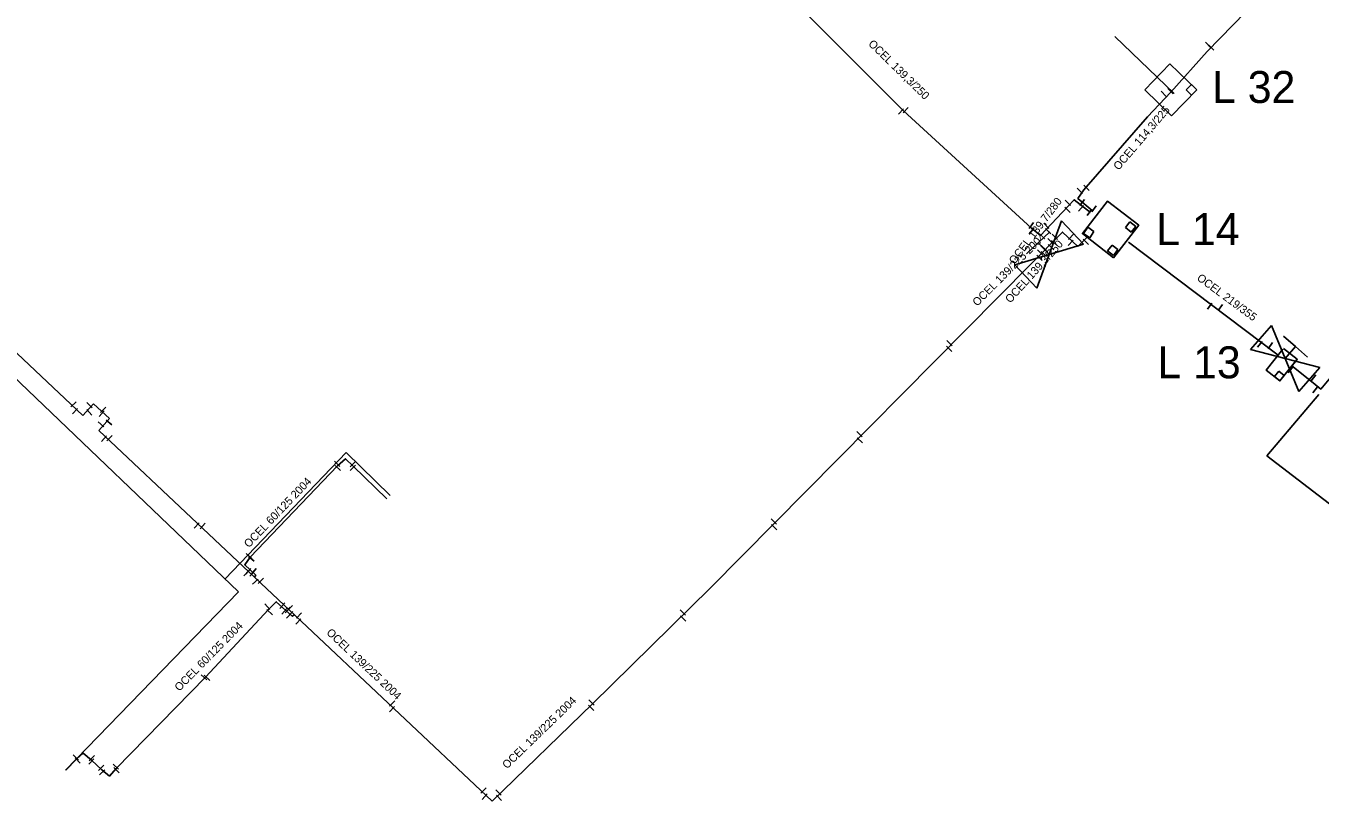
# Model space of a CAD drawing. Extents: x -642943 to -623314, y -1138561 to -1113539.
# Drawn here: x -641820 to -641698.7, y -1114182.4 to -1114109.7 of the extents above; entities that cross this region are included whole.
import ezdxf

# ---------------------------------------------------------------- set-up
doc = ezdxf.new("R2010")
doc.units = 0
for name, color, linetype in [('horkovod armatury', 7, 'Continuous'), ('horkovod dimenze', 7, 'Continuous'), ('horkovod předisol', 7, 'Continuous'), ('horkovod sváry', 7, 'Continuous'), ('horkovod trasa', 7, 'Continuous'), ('horkovod zrušený', 7, 'Continuous'), ('horkovod číslo šachty', 7, 'Continuous'), ('horkovod šachty', 7, 'Continuous')]:
    doc.layers.add(name, color=color, linetype=linetype)

# ---------------------------------------------------------------- blocks, each defined once
blk = doc.blocks.new('SPH')
at = {"layer": 'horkovod sváry'}
blk.add_line((0, -0.035), (0, 0.035), dxfattribs=at)
blk = doc.blocks.new('SPH_2')
at = {"layer": 'horkovod sváry'}
blk.add_line((0, -0.035), (0, 0.035), dxfattribs=at)
blk = doc.blocks.new('SPH_1')
at = {"layer": 'horkovod sváry'}
blk.add_line((0, -0.035), (0, 0.035), dxfattribs=at)
blk = doc.blocks.new('SCH_01_93')
at = {"layer": 'horkovod armatury'}
for p, q in [((10, 5), (-10, -5)), ((-10, -5), (-10, 5)), ((-10, 5), (10, -5)), ((-5, 5), (0, 5)), ((0, 5), (0, 0)), ((5, 5), (0, 5)), ((10, -5), (10, 5))]:
    blk.add_line(p, q, dxfattribs=at)
blk = doc.blocks.new('SCH_01_102')
at = {"layer": 'horkovod armatury'}
for p, q in [((10, 5), (-10, -5)), ((-10, -5), (-10, 5)), ((-10, 5), (10, -5)), ((-5, 5), (0, 5)), ((0, 5), (0, 0)), ((5, 5), (0, 5)), ((10, -5), (10, 5))]:
    blk.add_line(p, q, dxfattribs=at)
blk = doc.blocks.new('POINT_DISPLAY')
blk.add_line((0, 0), (0, 0))

msp = doc.modelspace()

# ---------------------------------------------------------------- linework, layer by layer
at = {"layer": 'horkovod předisol'}
for p, q in [((-641720.58, -1114129.52), (-641721.43, -1114130.36)), ((-641702.65, -1114140.55), (-641716.69, -1114129.96)), ((-641813.65, -1114145.13), (-641814.66, -1114146.23)), ((-641812.15, -1114146.51), (-641813.65, -1114145.13)), ((-641813.16, -1114147.61), (-641812.15, -1114146.51)), ((-641813.16, -1114147.61), (-641776.29, -1114182.38))]:
    msp.add_line(p, q, dxfattribs=at)
for points in [[(-641720.09, -1114126.99), (-641721.42, -1114125.86), (-641720.85, -1114125.06), (-641714.89, -1114118.2), (-641712.7, -1114115.88), (-641709.29, -1114112.08), (-641692.48, -1114094.76), (-641683.51, -1114085.54), (-641684.62, -1114084.43), (-641685.21, -1114083.62), (-641682.99, -1114081.4), (-641681.73, -1114082.64), (-641681.26, -1114083.19), (-641660.28, -1114061.53), (-641651.85, -1114053.53), (-641650.66, -1114052.42)], [(-641720.24, -1114127.19), (-641721.78, -1114125.98), (-641722.37, -1114126.63), (-641724.93, -1114129.34), (-641725.77, -1114128.66), (-641737.76, -1114117.63), (-641746.69, -1114108.69)], [(-641837.57, -1114124.6), (-641814.66, -1114146.23)], [(-641776.29, -1114182.38), (-641766.9, -1114173.26), (-641755.88, -1114162.41), (-641722.86, -1114129.02), (-641721.43, -1114130.36)], [(-641671.03, -1114175.33), (-641679.31, -1114168.85), (-641679.88, -1114168.36), (-641679.26, -1114167.36), (-641675.22, -1114162.06), (-641674.86, -1114161.43), (-641675.72, -1114160.68), (-641684.46, -1114152.48), (-641693.23, -1114144.31), (-641695.86, -1114141.92), (-641696.62, -1114141.3), (-641698.67, -1114143.74), (-641699.37, -1114143.14), (-641701.36, -1114141.55)], [(-641798.57, -1114161.37), (-641798.45, -1114161.2), (-641799.48, -1114160.23), (-641798.97, -1114159.51), (-641790.79, -1114150.94), (-641790.05, -1114150.27), (-641789.33, -1114150.98), (-641786.15, -1114154.02)], [(-641794.82, -1114164.91), (-641795.03, -1114165.04), (-641796.52, -1114163.69), (-641797.24, -1114164.4), (-641803.16, -1114170.77), (-641811.52, -1114179.31), (-641812.16, -1114180.03), (-641812.88, -1114179.44), (-641813.82, -1114178.53), (-641814.61, -1114177.87), (-641815.21, -1114178.42), (-641816.24, -1114179.49)]]:
    msp.add_lwpolyline(points, dxfattribs=at)
at = {"layer": 'horkovod trasa'}
for p, q in [((-641720.58, -1114129.52), (-641721.43, -1114130.36)), ((-641702.65, -1114140.55), (-641716.69, -1114129.96)), ((-641813.65, -1114145.13), (-641814.66, -1114146.23)), ((-641812.15, -1114146.51), (-641813.65, -1114145.13)), ((-641813.16, -1114147.61), (-641812.15, -1114146.51)), ((-641813.16, -1114147.61), (-641776.29, -1114182.38))]:
    msp.add_line(p, q, dxfattribs=at)
for points in [[(-641720.09, -1114126.99), (-641721.42, -1114125.86), (-641720.85, -1114125.06), (-641714.89, -1114118.2), (-641712.7, -1114115.88), (-641709.29, -1114112.08), (-641692.48, -1114094.76), (-641683.51, -1114085.54), (-641684.62, -1114084.43), (-641685.21, -1114083.62), (-641682.99, -1114081.4), (-641681.73, -1114082.64), (-641681.26, -1114083.19), (-641660.28, -1114061.53), (-641651.85, -1114053.53), (-641650.66, -1114052.42)], [(-641720.24, -1114127.19), (-641721.78, -1114125.98), (-641722.37, -1114126.63), (-641724.93, -1114129.34), (-641725.77, -1114128.66), (-641737.76, -1114117.63), (-641746.69, -1114108.69)], [(-641837.57, -1114124.6), (-641814.66, -1114146.23)], [(-641776.29, -1114182.38), (-641766.9, -1114173.26), (-641755.88, -1114162.41), (-641722.86, -1114129.02), (-641721.43, -1114130.36)], [(-641671.03, -1114175.33), (-641679.31, -1114168.85), (-641679.88, -1114168.36), (-641679.26, -1114167.36), (-641675.22, -1114162.06), (-641674.86, -1114161.43), (-641675.72, -1114160.68), (-641684.46, -1114152.48), (-641693.23, -1114144.31), (-641695.86, -1114141.92), (-641696.62, -1114141.3), (-641698.67, -1114143.74), (-641699.37, -1114143.14), (-641701.36, -1114141.55)], [(-641798.57, -1114161.37), (-641798.45, -1114161.2), (-641799.48, -1114160.23), (-641798.97, -1114159.51), (-641790.79, -1114150.94), (-641790.05, -1114150.27), (-641789.33, -1114150.98), (-641786.15, -1114154.02)], [(-641794.82, -1114164.91), (-641795.03, -1114165.04), (-641796.52, -1114163.69), (-641797.24, -1114164.4), (-641803.16, -1114170.77), (-641811.52, -1114179.31), (-641812.16, -1114180.03), (-641812.88, -1114179.44), (-641813.82, -1114178.53), (-641814.61, -1114177.87), (-641815.21, -1114178.42), (-641816.24, -1114179.49)]]:
    msp.add_lwpolyline(points, dxfattribs=at)
at = {"layer": 'horkovod zrušený'}
for p, q in [((-641712.39, -1114116.01), (-641717.97, -1114110.66)), ((-641800.05, -1114162.74), (-641836.18, -1114128.18)), ((-641703.7, -1114150), (-641698.84, -1114144.24)), ((-641801.31, -1114161.54), (-641789.96, -1114149.69)), ((-641789.96, -1114149.69), (-641785.86, -1114153.71)), ((-641689.17, -1114161.16), (-641703.7, -1114150)), ((-641816.28, -1114179.48), (-641800.05, -1114162.74))]:
    msp.add_line(p, q, dxfattribs=at)
at = {"layer": 'horkovod šachty'}
for p, q in [((-641712.79, -1114113.23), (-641715.16, -1114115.67)), ((-641710.28, -1114115.67), (-641712.79, -1114113.23)), ((-641711.27, -1114115.69), (-641710.78, -1114115.18)), ((-641710.28, -1114115.67), (-641710.78, -1114115.18)), ((-641715.16, -1114115.67), (-641712.65, -1114118.11)), ((-641712.65, -1114118.11), (-641710.28, -1114115.67)), ((-641711.27, -1114115.69), (-641710.77, -1114116.17)), ((-641710.77, -1114116.17), (-641710.28, -1114115.67)), ((-641720.48, -1114128.57), (-641720.88, -1114129.15)), ((-641719.91, -1114128.97), (-641720.48, -1114128.57)), ((-641716.54, -1114128.05), (-641716.97, -1114128.6)), ((-641716.97, -1114128.6), (-641716.41, -1114129.03)), ((-641715.98, -1114128.48), (-641716.54, -1114128.05)), ((-641716.41, -1114129.03), (-641715.98, -1114128.48)), ((-641720.88, -1114129.15), (-641720.31, -1114129.55)), ((-641720.31, -1114129.55), (-641719.91, -1114128.97)), ((-641718.22, -1114130.23), (-641718.65, -1114130.78)), ((-641718.65, -1114130.78), (-641718.09, -1114131.21)), ((-641717.66, -1114130.66), (-641718.22, -1114130.23)), ((-641718.09, -1114131.21), (-641717.66, -1114130.66)), ((-641702.6, -1114142.06), (-641703, -1114142.57)), ((-641702.08, -1114142.47), (-641702.6, -1114142.06)), ((-641703, -1114142.57), (-641702.49, -1114142.98)), ((-641702.49, -1114142.98), (-641702.08, -1114142.47))]:
    msp.add_line(p, q, dxfattribs=at)
for points in [[(-641718.07, -1114131.42), (-641715.72, -1114128.38), (-641718.64, -1114126.11), (-641721, -1114129.16), (-641718.07, -1114131.42)], [(-641702.22, -1114140.01), (-641703.77, -1114141.97), (-641702.49, -1114142.98), (-641700.88, -1114140.94), (-641702.15, -1114139.93)]]:
    msp.add_lwpolyline(points, dxfattribs=at)

# ---------------------------------------------------------------- block references
at = {"layer": 'horkovod armatury'}
for name, p, xscale, yscale, rotation in [('SCH_01_93', (-641724.11, -1114131.12), 0.3000413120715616, 0.30004131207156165, 43.47188790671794), ('SCH_01_102', (-641702.01, -1114140.88), 0.30002698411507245, 0.30002698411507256, -41.03534527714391)]:
    msp.add_blockref(name, p, dxfattribs=dict(at, xscale=xscale, yscale=yscale, rotation=rotation))
at = {"layer": 'horkovod sváry'}
for name, p, xscale, yscale, rotation in [('SPH_2', (-641709.23, -1114111.46), 10.000017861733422, 10.000017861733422, 44.742102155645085), ('SPH_2', (-641708.94, -1114111.7), 9.9999804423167, 9.9999804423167, 45.29185796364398), ('SPH_2', (-641713.38, -1114116.06), 10.000017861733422, 10.000017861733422, 44.742102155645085), ('SPH_2', (-641712.75, -1114115.79), 10.000017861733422, 10.000017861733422, 44.742102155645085), ('SPH_1', (-641737.98, -1114117.7), 9.99999033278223, 9.99999033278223, -42.62333940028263), ('SPH_2', (-641737.55, -1114117.57), 9.999999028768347, 9.999999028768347, -44.459671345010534), ('SPH_2', (-641721.23, -1114125.14), 9.999972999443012, 9.999972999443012, 43.902498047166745), ('SPH_2', (-641720.61, -1114124.86), 9.999998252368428, 9.999998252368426, 45.66541686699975), ('SPH_1', (-641722.36, -1114126.28), 10.000002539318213, 10.000002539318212, 42.7670283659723), ('SPH_2', (-641721.02, -1114126.25), 9.999991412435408, 9.99999141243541, -38.20174779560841), ('SPH_2', (-641722.38, -1114126.93), 9.999988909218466, 9.999988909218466, 46.01013601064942), ('SPH_2', (-641721.12, -1114126.79), 10.000003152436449, 10.00000315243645, -41.00586558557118), ('SPH_2', (-641720.35, -1114127.18), 9.999990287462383, 9.999990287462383, -33.96896854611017), ('SPH_2', (-641719.91, -1114126.83), 9.999998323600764, 9.999998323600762, -36.94070764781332), ('SPH_2', (-641725.79, -1114128.39), 9.999984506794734, 9.999984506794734, -36.282969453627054), ('SPH_2', (-641725.77, -1114128.92), 9.999986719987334, 9.999986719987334, -37.0851031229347), ('SPH_2', (-641724.37, -1114128.43), 10.000013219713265, 10.000013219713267, 41.58929200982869), ('SPH_2', (-641724.21, -1114128.92), 10.000013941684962, 10.000013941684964, 43.81494731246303), ('SPH', (-641723.98, -1114129.87), 10.000015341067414, 10.000015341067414, 45), ('SPH', (-641723.62, -1114130.04), 9.999993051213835, 9.999993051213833, -130.97163030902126), ('SPH', (-641723.57, -1114129.46), 10.000015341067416, 10.000015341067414, -135), ('SPH', (-641722.1, -1114130.03), 10.000005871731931, 10.000005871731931, -43.331827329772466), ('SPH', (-641722.05, -1114129.45), 10.000005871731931, 10.000005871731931, -43.331827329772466), ('SPH', (-641720.68, -1114129.92), 10.000002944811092, 10.00000294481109, -134.47759496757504), ('SPH', (-641720.63, -1114129.34), 10.000002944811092, 10.00000294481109, -134.47759496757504), ('SPH', (-641725.02, -1114131.43), 10.000002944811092, 10.00000294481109, -134.47759496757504), ('SPH', (-641724.96, -1114130.94), 9.999970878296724, 9.999970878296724, -135.18884897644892), ('SPH', (-641724.62, -1114130.51), 10.000015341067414, 10.000015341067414, 45), ('SPH', (-641724.6, -1114131.07), 10.000015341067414, 10.000015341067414, 45), ('SPH', (-641723.95, -1114130.42), 9.999993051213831, 9.999993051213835, 49.02836969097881), ('SPH_2', (-641709.06, -1114135.97), 9.999987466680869, 9.999987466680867, -34.79108359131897), ('SPH_2', (-641708.08, -1114136.1), 10.0000018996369, 10.0000018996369, -35.93086326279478), ('SPH', (-641733.45, -1114139.43), 10.00001721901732, 10.00001721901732, 45.79258215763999), ('SPH_2', (-641704.36, -1114139.54), 10.000002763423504, 10.000002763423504, -37.8349223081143), ('SPH_2', (-641703.38, -1114139.67), 9.999994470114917, 9.999994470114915, -34.892481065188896), ('SPH', (-641733.47, -1114139.96), 10.000003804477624, 10.000003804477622, 45.7731494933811), ('SPH', (-641701.51, -1114141.93), 10.000014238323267, 10.000014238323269, -39.019404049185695), ('SPH', (-641701.1, -1114141.24), 9.999981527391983, 9.99998152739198, -39.44944134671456), ('SPH', (-641699.35, -1114142.68), 9.999981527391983, 9.99998152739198, 140.55055865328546), ('SPH', (-641699.19, -1114143.81), 10.000014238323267, 10.000014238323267, 140.98059595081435), ('SPH', (-641815.53, -1114145.17), 9.999994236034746, 9.999994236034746, -45.93409473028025), ('SPH', (-641815.38, -1114145.81), 9.999998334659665, 9.999998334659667, -44.597774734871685), ('SPH', (-641814.04, -1114145.92), 9.999988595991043, 9.99998859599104, -136.04164725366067), ('SPH', (-641814.01, -1114145.25), 9.999985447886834, 9.999985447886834, -135.41826226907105), ('SPH', (-641812.73, -1114145.68), 10.000010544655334, 10.000010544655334, 134.3285464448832), ('SPH', (-641812.93, -1114147.04), 9.999990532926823, 9.999990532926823, 49.09475695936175), ('SPH', (-641812.88, -1114146.04), 9.999990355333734, 9.999990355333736, 137.602510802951), ('SPH', (-641812.2, -1114146.88), 9.999988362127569, 9.999988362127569, 49.73659987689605), ('SPH', (-641812.66, -1114148.39), 9.999995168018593, 9.999995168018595, -43.161197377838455), ('SPH', (-641812.15, -1114148.34), 9.9999991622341, 9.9999991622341, -43.34617035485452), ('SPH', (-641741.87, -1114147.97), 9.999999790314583, 9.999999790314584, 45.68220861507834), ('SPH', (-641741.86, -1114148.54), 9.99999587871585, 9.999995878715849, 46.033532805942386), ('SPH', (-641790.82, -1114150.75), 10.000000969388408, 10.00000096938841, -133.7134233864), ('SPH', (-641789.35, -1114150.78), 9.999998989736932, 9.999998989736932, -43.90457653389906), ('SPH', (-641790.75, -1114151.14), 9.999981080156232, 9.999981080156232, -134.03628039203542), ('SPH', (-641789.34, -1114151.12), 9.999992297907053, 9.999992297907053, -44.91944233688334), ('SPH', (-641803.98, -1114156.53), 9.999992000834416, 9.999992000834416, -43.68247407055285), ('SPH', (-641803.42, -1114156.58), 9.999988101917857, 9.999988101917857, -43.55056197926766), ('SPH', (-641749.89, -1114156.16), 9.999971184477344, 9.999971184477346, 45.684285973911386), ('SPH', (-641749.86, -1114156.69), 10.000002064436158, 10.000002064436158, 45.47863442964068), ('SPH', (-641799.07, -1114159.39), 10.000019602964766, 10.000019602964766, -129.34671863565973), ('SPH', (-641798.87, -1114159.65), 10.000005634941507, 10.000005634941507, -130.29199291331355), ('SPH', (-641799.31, -1114160.99), 10.00000238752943, 10.00000238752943, -42.51061097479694), ('SPH', (-641799.13, -1114160.84), 10.000009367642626, 10.000009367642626, -41.46813781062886), ('SPH', (-641798.76, -1114161.01), 9.999979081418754, 9.999979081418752, -41.08168925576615), ('SPH', (-641798.62, -1114160.82), 10.000001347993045, 10.000001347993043, -40.601236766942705), ('SPH', (-641797.97, -1114161.72), 9.99998971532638, 9.99998971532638, 137.23108647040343), ('SPH', (-641798.48, -1114161.81), 10.000019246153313, 10.000019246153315, 132.6467599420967), ('SPH', (-641797.35, -1114164.14), 9.999990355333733, 9.999990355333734, 42.397489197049), ('SPH', (-641795.94, -1114164.05), 10.000020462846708, 10.000020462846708, 138.30185118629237), ('SPH', (-641797.14, -1114164.66), 9.999996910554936, 9.999996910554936, 46.443963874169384), ('SPH', (-641795.78, -1114164.58), 10.000008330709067, 10.000008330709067, 138.1221578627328), ('SPH', (-641795.45, -1114164.46), 10.00000522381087, 10.000005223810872, 140.07951181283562), ('SPH', (-641795.33, -1114164.97), 10.000000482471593, 10.000000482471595, -43.884575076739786), ('SPH', (-641795.25, -1114164.28), 9.999978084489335, 9.999978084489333, 136.64307506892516), ('SPH', (-641795.2, -1114164.84), 10.00001759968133, 10.000017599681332, 137.12101260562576), ('SPH', (-641794.4, -1114164.98), 10.0000112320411, 10.000011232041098, -43.537921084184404), ('SPH', (-641758.42, -1114164.7), 10.000000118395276, 10.000000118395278, 45.346003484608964), ('SPH', (-641758.4, -1114165.25), 9.999970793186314, 9.999970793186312, 45.23922154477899), ('SPH', (-641794.45, -1114165.53), 10.000011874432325, 10.000011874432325, -43.36334752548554), ('SPH', (-641803.3, -1114170.76), 10.000005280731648, 10.000005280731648, 47.92511272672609), ('SPH', (-641803.01, -1114170.81), 9.999989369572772, 9.999989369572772, 46.169016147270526), ('SPH', (-641785.68, -1114173.76), 10.000025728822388, 10.000025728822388, -43.42789645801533), ('SPH', (-641785.67, -1114173.23), 10.000003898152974, 10.000003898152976, -43.77286576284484), ('SPH', (-641767.01, -1114173.62), 9.99999759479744, 9.99999759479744, 44.22949149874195), ('SPH', (-641766.98, -1114173.13), 9.99999569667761, 9.99999569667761, 44.90661350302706), ('SPH', (-641815.3, -1114178.29), 9.999997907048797, 9.999997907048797, 43.07455643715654), ('SPH', (-641815.13, -1114178.57), 10.000011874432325, 10.000011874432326, 43.363347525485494), ('SPH', (-641813.85, -1114178.67), 10.000015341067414, 10.000015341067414, -45.00000000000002), ('SPH', (-641813.81, -1114178.36), 9.999977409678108, 9.999977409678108, -45.323742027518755), ('SPH', (-641812.93, -1114179.25), 9.999982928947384, 9.999982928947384, 135.79201884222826), ('SPH', (-641812.84, -1114179.68), 9.999999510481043, 9.999999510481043, 135.23337236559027), ('SPH', (-641811.54, -1114179.15), 9.999997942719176, 9.999997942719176, 45.596740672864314), ('SPH', (-641811.48, -1114179.48), 10.000013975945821, 10.000013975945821, 46.20316789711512), ('SPH', (-641777.11, -1114181.39), 10.000015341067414, 10.000015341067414, -45.00000000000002), ('SPH', (-641777, -1114181.95), 9.999985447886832, 9.999985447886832, -41.30858364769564), ('SPH', (-641775.7, -1114181.57), 10.000011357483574, 10.000011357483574, 43.96156285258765), ('SPH', (-641775.65, -1114182.06), 10.000018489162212, 10.000018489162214, 44.447975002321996)]:
    msp.add_blockref(name, p, dxfattribs=dict(at, xscale=xscale, yscale=yscale, rotation=rotation))
at = {"layer": 'horkovod šachty'}
for p in [(-641710.77, -1114115.68), (-641716.47, -1114128.54), (-641720.39, -1114129.06), (-641718.15, -1114130.72), (-641702.53, -1114142.52)]:
    msp.add_blockref('POINT_DISPLAY', p, dxfattribs=at)

# ---------------------------------------------------------------- texts
at = {"layer": 'horkovod dimenze'}
for s, rotation, p in [('OCEL 139,3/250', 315.5736, (-641741.11, -1114111.43)), ('OCEL 114,3/225', 49.4735, (-641717.6, -1114123.27)), ('OCEL 139,7/280', 53.0354, (-641727.35, -1114132.1)), ('OCEL 139/225 2004', 45, (-641730.85, -1114136.02)), ('OCEL 139,3/250', 47.963, (-641727.75, -1114135.73)), ('OCEL 219/355', 323.488, (-641710.33, -1114133.46)), ('OCEL 60/125 2004', 46.3228, (-641799.09, -1114158.67)), ('OCEL 60/125 2004', 45.5168, (-641805.6, -1114172.13)), ('OCEL 139/225 2004', 316.6192, (-641791.88, -1114166.65)), ('OCEL 139/225 2004', 44.0652, (-641774.91, -1114179.4))]:
    msp.add_text(s, height=0.75, rotation=rotation, dxfattribs=at).set_placement(p)
at = {"layer": 'horkovod číslo šachty'}
for s, p in [('L 32', (-641708.85, -1114116.91)), ('L 14', (-641714.07, -1114130.24)), ('L 13', (-641713.97, -1114142.73))]:
    msp.add_text(s, height=3, dxfattribs=at).set_placement(p)

doc.saveas('drawing.dxf')
